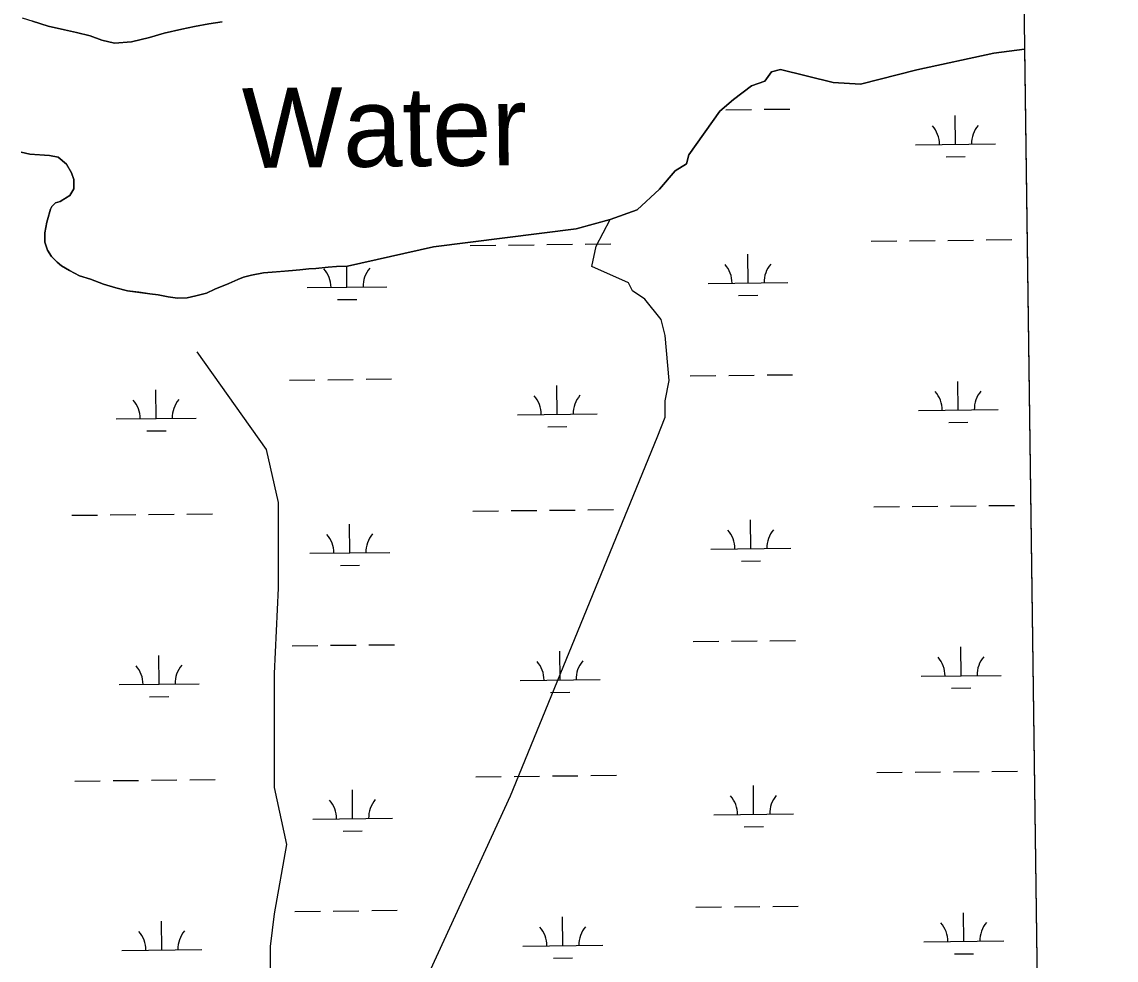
# Model space of a CAD drawing. Extents: x 3734862 to 3772949, y 391520 to 417239.
# Drawn here: x 3769474 to 3770844, y 404651 to 405826 of the extents above; entities that cross this region are included whole.
import ezdxf

# ---------------------------------------------------------------- set-up
doc = ezdxf.new("R2010")
doc.units = 0
for name, color, linetype in [('V-GRID-FRAM', 7, 'Continuous'), ('V-RIVR-IDEN', 7, 'Continuous'), ('V-TOPO-SHOR', 7, 'Continuous'), ('V-WETL-SWMP', 7, 'Continuous')]:
    doc.layers.add(name, color=color, linetype=linetype)

msp = doc.modelspace()

# ---------------------------------------------------------------- linework, layer by layer
at = {"layer": 'V-GRID-FRAM'}
msp.add_lwpolyline([(3738832.3, 415033.8), (3770599.2, 415447.4), (3770843.8, 397266.6), (3739061.1, 396852.8), (3738832.3, 415033.8)], dxfattribs=at)
at = {"layer": 'V-TOPO-SHOR'}
for p, q in [((3769487.8, 405826.9), (3769507.3, 405820.6)), ((3769507.3, 405820.6), (3769527.6, 405815.8)), ((3769527.6, 405815.8), (3769542.8, 405812.6)), ((3769652.4, 405811.8), (3769674.3, 405816.8)), ((3769674.3, 405816.8), (3769690.3, 405820.3)), ((3769690.3, 405820.3), (3769708.3, 405823.7)), ((3769708.3, 405823.7), (3769725, 405826)), ((3769542.8, 405812.6), (3769559.9, 405808.3)), ((3769559.9, 405808.3), (3769574.3, 405803.1)), ((3769574.3, 405803.1), (3769590.3, 405799.2)), ((3769590.3, 405799.2), (3769611.4, 405801)), ((3769611.4, 405801), (3769634.1, 405806.4)), ((3769634.1, 405806.4), (3769652.4, 405811.8)), ((3770690.8, 405787), (3770594.5, 405765.8)), ((3770729.1, 405791.8), (3770690.8, 405787)), ((3770412.6, 405763.3), (3770404.3, 405751.9)), ((3770423.9, 405766.3), (3770412.6, 405763.3)), ((3770489.5, 405750.2), (3770423.9, 405766.3)), ((3770594.5, 405765.8), (3770523.7, 405747.8)), ((3770387.3, 405745.9), (3770364.8, 405728.6)), ((3770404.3, 405751.9), (3770387.3, 405745.9)), ((3770523.7, 405747.8), (3770489.5, 405750.2)), ((3770364.8, 405728.6), (3770347.9, 405714.1)), ((3770347.9, 405714.1), (3770308.9, 405659.6)), ((3769484.2, 405660.5), (3769473.3, 405662.8)), ((3769496.2, 405659.6), (3769484.2, 405660.5)), ((3769508.7, 405658.8), (3769496.2, 405659.6)), ((3769519.9, 405656.4), (3769508.7, 405658.8)), ((3769530, 405647.9), (3769519.9, 405656.4)), ((3770308.9, 405659.6), (3770306.2, 405648.2)), ((3769536.6, 405636.9), (3769530, 405647.9)), ((3769539.3, 405628.8), (3769536.6, 405636.9)), ((3770292.1, 405639.5), (3770272.5, 405616.5)), ((3770306.2, 405648.2), (3770292.1, 405639.5)), ((3769539.2, 405617.1), (3769539.3, 405628.8)), ((3769534.5, 405608.6), (3769539.2, 405617.1)), ((3770272.5, 405616.5), (3770244.5, 405590.5)), ((3769511.9, 405594.7), (3769516.6, 405599.3)), ((3769516.6, 405599.3), (3769522.1, 405601.2)), ((3769522.1, 405601.2), (3769526.7, 405603.9)), ((3769526.7, 405603.9), (3769534.5, 405608.6)), ((3769507.2, 405581.1), (3769510, 405591.6)), ((3769510, 405591.6), (3769511.9, 405594.7)), ((3770244.5, 405590.5), (3770210.5, 405578.7)), ((3769503.2, 405562), (3769504.8, 405570.6)), ((3769504.8, 405570.6), (3769505.6, 405575.3)), ((3769505.6, 405575.3), (3769507.2, 405581.1)), ((3770210.5, 405578.7), (3770168.1, 405566.7)), ((3769503.2, 405550), (3769503.2, 405562)), ((3770168.1, 405566.7), (3769989.3, 405544.4)), ((3769506.3, 405540.3), (3769503.2, 405550)), ((3769511.3, 405532.1), (3769506.3, 405540.3)), ((3769989.3, 405544.4), (3769881.7, 405520.2)), ((3769518.3, 405525.1), (3769511.3, 405532.1)), ((3769524.1, 405520.4), (3769518.3, 405525.1)), ((3769533.8, 405514.5), (3769524.1, 405520.4)), ((3769546.6, 405508.2), (3769533.8, 405514.5)), ((3769798.5, 405513.5), (3769787.6, 405512.8)), ((3769812.9, 405514.6), (3769798.5, 405513.5)), ((3769822.2, 405515.7), (3769812.9, 405514.6)), ((3769833.5, 405516.9), (3769822.2, 405515.7)), ((3769842.4, 405517.2), (3769833.5, 405516.9)), ((3769857.6, 405518.7), (3769842.4, 405517.2)), ((3769868.1, 405519.5), (3769857.6, 405518.7)), ((3769881.7, 405520.2), (3769868.1, 405519.5)), ((3769560.2, 405503.9), (3769546.6, 405508.2)), ((3769576.5, 405497.6), (3769560.2, 405503.9)), ((3769744.8, 405503.6), (3769733.5, 405498.6)), ((3769751.8, 405506.3), (3769744.8, 405503.6)), ((3769761.9, 405509), (3769751.8, 405506.3)), ((3769776.7, 405511.6), (3769761.9, 405509)), ((3769787.6, 405512.8), (3769776.7, 405511.6)), ((3769592, 405492.9), (3769576.5, 405497.6)), ((3769606.4, 405489.4), (3769592, 405492.9)), ((3769620.7, 405487.4), (3769606.4, 405489.4)), ((3769634.3, 405485.4), (3769620.7, 405487.4)), ((3769705.5, 405486.3), (3769692.2, 405482.8)), ((3769716, 405491.3), (3769705.5, 405486.3)), ((3769733.5, 405498.6), (3769716, 405491.3)), ((3769644.8, 405484.2), (3769634.3, 405485.4)), ((3769657.6, 405481.8), (3769644.8, 405484.2)), ((3769668.9, 405480.2), (3769657.6, 405481.8)), ((3769681, 405480.5), (3769668.9, 405480.2)), ((3769692.2, 405482.8), (3769681, 405480.5))]:
    msp.add_line(p, q, dxfattribs=at)
for points in [[(3769725, 405826), (3769708.3, 405823.7), (3769690.3, 405820.3), (3769674.3, 405816.8), (3769652.4, 405811.8), (3769634.1, 405806.4), (3769611.4, 405801), (3769590.3, 405799.2), (3769574.3, 405803.1), (3769559.9, 405808.3), (3769542.8, 405812.6), (3769527.6, 405815.8), (3769507.3, 405820.6), (3769487.8, 405826.9)], [(3769881.7, 405520.2), (3769989.3, 405544.4), (3770168.1, 405566.7), (3770210.5, 405578.7), (3770244.5, 405590.5), (3770272.5, 405616.5), (3770292.1, 405639.5), (3770306.2, 405648.2), (3770308.9, 405659.6), (3770347.9, 405714.1), (3770364.8, 405728.6), (3770387.3, 405745.9), (3770404.3, 405751.9), (3770412.6, 405763.3), (3770423.9, 405766.3), (3770489.5, 405750.2), (3770523.7, 405747.8), (3770594.5, 405765.8), (3770690.8, 405787), (3770729.1, 405791.8)], [(3769881.7, 405520.2), (3769868.1, 405519.5), (3769857.6, 405518.7), (3769842.4, 405517.2), (3769833.5, 405516.9), (3769822.2, 405515.7), (3769812.9, 405514.6), (3769798.5, 405513.5), (3769787.6, 405512.8), (3769776.7, 405511.6), (3769761.9, 405509), (3769751.8, 405506.3), (3769744.8, 405503.6), (3769733.5, 405498.6), (3769716, 405491.3), (3769705.5, 405486.3), (3769692.2, 405482.8), (3769681, 405480.5), (3769668.9, 405480.2), (3769657.6, 405481.8), (3769644.8, 405484.2), (3769634.3, 405485.4), (3769620.7, 405487.4), (3769606.4, 405489.4), (3769592, 405492.9), (3769576.5, 405497.6), (3769560.2, 405503.9), (3769546.6, 405508.2), (3769533.8, 405514.5), (3769524.1, 405520.4), (3769518.3, 405525.1), (3769511.3, 405532.1), (3769506.3, 405540.3), (3769503.2, 405550), (3769503.2, 405562), (3769504.8, 405570.6), (3769505.6, 405575.3), (3769507.2, 405581.1), (3769510, 405591.6), (3769511.9, 405594.7), (3769516.6, 405599.3), (3769522.1, 405601.2), (3769526.7, 405603.9), (3769534.5, 405608.6), (3769539.2, 405617.1), (3769539.3, 405628.8), (3769536.6, 405636.9), (3769530, 405647.9), (3769519.9, 405656.4), (3769508.7, 405658.8), (3769496.2, 405659.6), (3769484.2, 405660.5), (3769473.3, 405662.8)], [(3769865.3, 404376.6), (3770085.8, 404857.1), (3770269.3, 405305.7), (3770279.5, 405331.2), (3770279.5, 405351.6), (3770284.6, 405377.1), (3770279.5, 405433.1), (3770274.4, 405453.5), (3770254, 405479), (3770238.7, 405489.2), (3770233.6, 405499.4), (3770187.8, 405519.8), (3770192.9, 405545.3), (3770210.5, 405578.7)], [(3769693.3, 405412.7), (3769779.9, 405290.4), (3769795.2, 405224.1), (3769795.2, 405117.1), (3769790.1, 405010), (3769790.1, 404928.5), (3769790.1, 404867.3), (3769805.4, 404795.9), (3769790.1, 404709.3), (3769785, 404668.5), (3769785, 404612.4), (3769785, 404581.8), (3769779.9, 404546.1), (3769779.9, 404490.1), (3769785, 404459.5), (3769805.4, 404434), (3769846.2, 404398.3), (3769865.3, 404376.6)]]:
    msp.add_lwpolyline(points, dxfattribs=at)
at = {"layer": 'V-WETL-SWMP'}
for p, q in [((3769507.3, 405820.6), (3769475.3, 405830.8)), ((3769527.6, 405815.8), (3769507.3, 405820.6)), ((3769542.8, 405812.6), (3769527.6, 405815.8)), ((3769674.3, 405816.8), (3769652.4, 405811.8)), ((3769690.3, 405820.3), (3769674.3, 405816.8)), ((3769708.3, 405823.7), (3769690.3, 405820.3)), ((3769725, 405826), (3769708.3, 405823.7)), ((3769559.9, 405808.3), (3769542.8, 405812.6)), ((3769574.3, 405803.1), (3769559.9, 405808.3)), ((3769590.3, 405799.2), (3769574.3, 405803.1)), ((3769611.4, 405801), (3769590.3, 405799.2)), ((3769634.1, 405806.4), (3769611.4, 405801)), ((3769652.4, 405811.8), (3769634.1, 405806.4)), ((3770594.5, 405765.8), (3770690.8, 405787)), ((3770690.8, 405787), (3770729.1, 405791.8)), ((3770729.1, 405791.8), (3770755, 403867.5)), ((3770404.3, 405751.9), (3770412.6, 405763.3)), ((3770412.6, 405763.3), (3770423.9, 405766.3)), ((3770423.9, 405766.3), (3770489.5, 405750.2)), ((3770523.7, 405747.8), (3770594.5, 405765.8)), ((3770364.8, 405728.6), (3770387.3, 405745.9)), ((3770387.3, 405745.9), (3770404.3, 405751.9)), ((3770489.5, 405750.2), (3770523.7, 405747.8)), ((3770347.9, 405714.1), (3770364.8, 405728.6)), ((3770308.9, 405659.6), (3770347.9, 405714.1)), ((3770355.4, 405716), (3770387.4, 405716.3)), ((3770403.4, 405716.5), (3770435.4, 405716.8)), ((3770642.7, 405672.6), (3770642.4, 405708.6)), ((3770592.7, 405672.1), (3770692.7, 405673.1)), ((3769473.3, 405662.8), (3769484.2, 405660.5)), ((3769484.2, 405660.5), (3769508.7, 405658.8)), ((3769508.7, 405658.8), (3769519.9, 405656.4)), ((3769519.9, 405656.4), (3769530, 405647.9)), ((3770306.2, 405648.2), (3770308.9, 405659.6)), ((3770630.9, 405657), (3770654.9, 405657.3)), ((3769530, 405647.9), (3769536.6, 405636.9)), ((3769536.6, 405636.9), (3769539.3, 405628.8)), ((3770272.5, 405616.5), (3770292.1, 405639.5)), ((3770292.1, 405639.5), (3770306.2, 405648.2)), ((3769539.3, 405628.8), (3769539.2, 405617.1)), ((3769539.2, 405617.1), (3769534.5, 405608.6)), ((3770244.5, 405590.5), (3770272.5, 405616.5)), ((3769516.6, 405599.3), (3769511.9, 405594.7)), ((3769522.1, 405601.2), (3769516.6, 405599.3)), ((3769534.5, 405608.6), (3769522.1, 405601.2)), ((3769510, 405591.6), (3769505.6, 405575.3)), ((3769511.9, 405594.7), (3769510, 405591.6)), ((3770210.5, 405578.7), (3770244.5, 405590.5)), ((3769505.6, 405575.3), (3769503.2, 405562)), ((3770168.1, 405566.7), (3770210.5, 405578.7)), ((3769503.2, 405562), (3769503.2, 405550)), ((3769989.3, 405544.4), (3770168.1, 405566.7)), ((3769503.2, 405550), (3769506.3, 405540.3)), ((3769506.3, 405540.3), (3769511.3, 405532.1)), ((3769881.7, 405520.2), (3769989.3, 405544.4)), ((3770035.3, 405546.1), (3770067.3, 405546.5)), ((3770083.3, 405546.6), (3770115.3, 405547)), ((3770131.3, 405547.1), (3770163.3, 405547.5)), ((3770179.3, 405547.6), (3770211.3, 405548)), ((3770537.2, 405551.4), (3770569.2, 405551.8)), ((3770585.2, 405551.9), (3770617.2, 405552.3)), ((3770633.2, 405552.4), (3770665.2, 405552.8)), ((3770681.2, 405552.9), (3770713.2, 405553.3)), ((3769511.3, 405532.1), (3769518.3, 405525.1)), ((3770383.1, 405499), (3770382.7, 405535)), ((3769518.3, 405525.1), (3769524.1, 405520.4)), ((3769524.1, 405520.4), (3769533.8, 405514.5)), ((3769533.8, 405514.5), (3769546.6, 405508.2)), ((3769787.6, 405512.8), (3769812.9, 405514.6)), ((3769812.9, 405514.6), (3769822.2, 405515.7)), ((3769822.2, 405515.7), (3769833.5, 405516.9)), ((3769833.5, 405516.9), (3769842.4, 405517.2)), ((3769842.4, 405517.2), (3769857.6, 405518.7)), ((3769857.6, 405518.7), (3769868.1, 405519.5)), ((3769868.1, 405519.5), (3769881.7, 405520.2)), ((3769881.2, 405493.7), (3769881, 405520.1)), ((3769546.6, 405508.2), (3769560.2, 405503.9)), ((3769560.2, 405503.9), (3769576.5, 405497.6)), ((3769733.5, 405498.6), (3769744.8, 405503.6)), ((3769744.8, 405503.6), (3769751.8, 405506.3)), ((3769751.8, 405506.3), (3769761.9, 405509)), ((3769761.9, 405509), (3769776.7, 405511.6)), ((3769776.7, 405511.6), (3769787.6, 405512.8)), ((3770333.1, 405498.5), (3770433.1, 405499.6)), ((3769576.5, 405497.6), (3769592, 405492.9)), ((3769592, 405492.9), (3769606.4, 405489.4)), ((3769606.4, 405489.4), (3769634.3, 405485.4)), ((3769692.2, 405482.8), (3769705.5, 405486.3)), ((3769705.5, 405486.3), (3769716, 405491.3)), ((3769716, 405491.3), (3769733.5, 405498.6)), ((3769831.2, 405493.2), (3769931.2, 405494.3)), ((3769634.3, 405485.4), (3769644.8, 405484.2)), ((3769644.8, 405484.2), (3769657.6, 405481.8)), ((3769657.6, 405481.8), (3769668.9, 405480.2)), ((3769668.9, 405480.2), (3769681, 405480.5)), ((3769681, 405480.5), (3769692.2, 405482.8)), ((3769869.4, 405478.2), (3769893.4, 405478.4)), ((3770371.3, 405483.5), (3770395.3, 405483.7)), ((3769809.1, 405377.5), (3769841.1, 405377.9)), ((3769857.1, 405378), (3769889.1, 405378.4)), ((3769905.1, 405378.6), (3769937, 405378.9)), ((3770310.9, 405382.8), (3770342.9, 405383.2)), ((3770358.9, 405383.3), (3770390.9, 405383.7)), ((3770406.9, 405383.9), (3770438.9, 405384.2)), ((3770646.3, 405339.9), (3770645.9, 405375.9)), ((3769642.5, 405329.3), (3769642.1, 405365.3)), ((3770144.4, 405334.6), (3770144, 405370.6)), ((3770094.4, 405334.1), (3770194.4, 405335.2)), ((3770596.3, 405339.4), (3770696.2, 405340.5)), ((3769592.5, 405328.8), (3769692.5, 405329.9)), ((3770634.4, 405324.4), (3770658.4, 405324.6)), ((3769630.7, 405313.8), (3769654.7, 405314)), ((3770132.5, 405319.1), (3770156.5, 405319.3)), ((3770038.8, 405213.5), (3770070.8, 405213.8)), ((3770086.8, 405214), (3770118.8, 405214.3)), ((3770134.8, 405214.5), (3770166.8, 405214.8)), ((3770182.8, 405215), (3770214.8, 405215.3)), ((3770540.7, 405218.8), (3770572.7, 405219.1)), ((3770588.7, 405219.3), (3770620.7, 405219.6)), ((3770636.7, 405219.8), (3770668.7, 405220.1)), ((3770684.7, 405220.3), (3770716.7, 405220.6)), ((3769536.9, 405208.2), (3769568.9, 405208.5)), ((3769584.9, 405208.7), (3769616.9, 405209)), ((3769632.9, 405209.2), (3769664.9, 405209.5)), ((3769680.9, 405209.7), (3769712.9, 405210)), ((3770386.6, 405166.4), (3770386.3, 405202.4)), ((3769884.8, 405161.1), (3769884.4, 405197.1)), ((3769834.8, 405160.6), (3769934.8, 405161.6)), ((3770336.6, 405165.9), (3770436.6, 405166.9)), ((3769872.9, 405145.5), (3769896.9, 405145.8)), ((3770374.8, 405150.8), (3770398.8, 405151.1)), ((3770314.5, 405050.2), (3770346.4, 405050.5)), ((3770362.4, 405050.7), (3770394.4, 405051)), ((3770410.4, 405051.2), (3770442.4, 405051.5)), ((3769812.6, 405044.9), (3769844.6, 405045.2)), ((3769860.6, 405045.4), (3769892.6, 405045.7)), ((3769908.6, 405045.9), (3769940.6, 405046.2)), ((3770147.9, 405002), (3770147.5, 405038)), ((3770649.8, 405007.3), (3770649.4, 405043.3)), ((3769646, 404996.7), (3769645.6, 405032.7)), ((3770599.8, 405006.8), (3770699.8, 405007.8)), ((3769596, 404996.2), (3769696, 404997.2)), ((3770097.9, 405001.5), (3770197.9, 405002.5)), ((3769634.2, 404981.1), (3769658.2, 404981.4)), ((3770136, 404986.4), (3770160, 404986.7)), ((3770637.9, 404991.7), (3770661.9, 404992)), ((3770544.2, 404886.1), (3770576.2, 404886.4)), ((3770592.2, 404886.6), (3770624.2, 404886.9)), ((3770640.2, 404887.1), (3770672.2, 404887.5)), ((3770688.2, 404887.6), (3770720.2, 404888)), ((3769540.4, 404875.5), (3769572.4, 404875.8)), ((3769588.4, 404876), (3769620.4, 404876.3)), ((3769636.4, 404876.5), (3769668.4, 404876.9)), ((3769684.4, 404877), (3769716.4, 404877.4)), ((3770042.3, 404880.8), (3770074.3, 404881.1)), ((3770090.3, 404881.3), (3770122.3, 404881.6)), ((3770138.3, 404881.8), (3770170.3, 404882.2)), ((3770186.3, 404882.3), (3770218.3, 404882.7)), ((3770390.1, 404833.7), (3770389.8, 404869.7)), ((3769888.3, 404828.4), (3769887.9, 404864.4)), ((3769838.3, 404827.9), (3769938.3, 404829)), ((3770340.2, 404833.2), (3770440.1, 404834.3)), ((3770378.3, 404818.2), (3770402.3, 404818.4)), ((3769876.4, 404812.9), (3769900.4, 404813.1)), ((3770414, 404718.5), (3770446, 404718.9)), ((3769816.1, 404712.2), (3769848.1, 404712.6)), ((3769864.1, 404712.7), (3769896.1, 404713.1)), ((3769912.1, 404713.2), (3769944.1, 404713.6)), ((3770151.4, 404669.3), (3770151, 404705.3)), ((3770318, 404717.5), (3770350, 404717.9)), ((3770366, 404718), (3770398, 404718.4)), ((3770653.3, 404674.6), (3770652.9, 404710.6)), ((3769649.5, 404664), (3769649.1, 404700)), ((3769599.5, 404663.5), (3769699.5, 404664.6)), ((3770101.4, 404668.8), (3770201.4, 404669.9)), ((3770603.3, 404674.1), (3770703.3, 404675.2)), ((3770139.6, 404653.8), (3770163.6, 404654)), ((3770641.4, 404659.1), (3770665.4, 404659.3))]:
    msp.add_line(p, q, dxfattribs=at)
for centre, start, end in [((3770587.5, 405672.5), 359.8334, 41.377), ((3770698, 405673.7), 139.8334, 181.377), ((3769826, 405493.6), 359.8334, 41.377), ((3769936.5, 405494.8), 139.8334, 181.377), ((3770327.9, 405498.9), 359.8334, 41.377), ((3770438.4, 405500.1), 139.8334, 181.377), ((3770591, 405339.8), 359.8334, 41.377), ((3770701.5, 405341), 139.8334, 181.377), ((3769587.2, 405329.2), 359.8334, 41.377), ((3769697.7, 405330.4), 139.8334, 181.377), ((3770089.1, 405334.5), 359.8334, 41.377), ((3770199.6, 405335.7), 139.8334, 181.377), ((3769829.5, 405161), 359.8334, 41.377), ((3769940, 405162.1), 139.8334, 181.377), ((3770331.4, 405166.3), 359.8334, 41.377), ((3770441.9, 405167.4), 139.8334, 181.377), ((3769590.8, 404996.6), 359.8334, 41.377), ((3769701.2, 404997.7), 139.8334, 181.377), ((3770092.6, 405001.9), 359.8334, 41.377), ((3770203.1, 405003.1), 139.8334, 181.377), ((3770594.5, 405007.2), 359.8334, 41.377), ((3770705, 405008.4), 139.8334, 181.377), ((3770334.9, 404833.6), 359.8334, 41.377), ((3770445.4, 404834.8), 139.8334, 181.377), ((3769833, 404828.3), 359.8334, 41.377), ((3769943.5, 404829.5), 139.8334, 181.377), ((3770096.2, 404669.2), 359.8334, 41.377), ((3770206.6, 404670.4), 139.8334, 181.377), ((3770598, 404674.5), 359.8334, 41.377), ((3770708.5, 404675.7), 139.8334, 181.377), ((3769594.3, 404663.9), 359.8334, 41.377), ((3769704.8, 404665.1), 139.8334, 181.377)]:
    msp.add_arc(centre, 35.2, start, end, dxfattribs=at)

# ---------------------------------------------------------------- texts
at = {"layer": 'V-RIVR-IDEN'}
msp.add_text('Water', height=100, rotation=0.6, dxfattribs=at).set_placement((3769750.4, 405642.9))

doc.saveas('drawing.dxf')
